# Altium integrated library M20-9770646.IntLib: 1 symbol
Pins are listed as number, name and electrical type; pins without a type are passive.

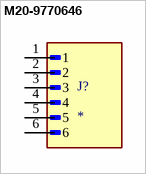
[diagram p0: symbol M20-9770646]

## M20-9770646
designator J?
MP: M20-9770646
footprint HARWIN_M20-9770646
pins: 1, 2, 3, 4, 5, 6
